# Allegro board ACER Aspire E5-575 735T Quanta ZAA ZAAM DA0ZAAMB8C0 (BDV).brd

Outline 244.9 x 198.7 mm; copper layers: TOP, SGND, IN1, SVCC, IN2, IN3, SGND1, BOTTOM. Coordinates in mm from the lower left corner of the outline.

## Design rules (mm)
constraint set DEFAULT: min track width 0.127
net group DFP-S5W4.5(5)-T13B: nets DDCCLK DDCDAT
net group DFP-S5W5-T: nets USBP0+_R USBP0-_R
net group DFP-S20(10)W16(18)-T123B: nets VGA_VCCSENSE VGA_VSSSENSE
net group W12-T123B: nets PCIE_RCOMPN PCIE_RCOMPP
net group W25-T123B: nets +3V_RTC VCCRTC_2
net group W35-T123B: nets AVCC33 VDD_DAC_33
net group W80-T123B: nets +5V_HDD +5V_ODD
net group W99-T123B: nets USBPWR1 USBPWRD2
net group DFP-S3.5(3)W5(3.5)-T13B: nets VMA_CLK0 VMA_CLK0# VMA_CLK1 VMA_CLK1# VMB_CLK0 VMB_CLK0# VMB_CLK1 VMB_CLK1#
net group DFP-S3.5(3: nets VMA_WCK01 VMA_WCK01# VMA_WCK23 VMA_WCK23# VMA_WCK45 VMA_WCK45# VMA_WCK67 VMA_WCK67# VMB_WCK01 VMB_WCK01# VMB_WCK23 VMB_WCK23# VMB_WCK45 VMB_WCK45# VMB_WCK67 VMB_WCK67#
net group DFP-S4.5(3.5: nets M_A_DQS0 M_A_DQS1 M_A_DQS2 M_A_DQS3 M_A_DQS4 M_A_DQS5 M_A_DQS6 M_A_DQS7 M_A_DQS#0 M_A_DQS#1 M_A_DQS#2 M_A_DQS#3 M_A_DQS#4 M_A_DQS#5 M_A_DQS#6 M_A_DQS#7 M_B_DQS0 M_B_DQS1 M_B_DQS2 M_B_DQS3 M_B_DQS4 M_B_DQS5 M_B_DQS6 M_B_DQS7 M_B_DQS#0 M_B_DQS#1 M_B_DQS#2 M_B_DQS#3 M_B_DQS#4 M_B_DQS#5 M_B_DQS#6 M_B_DQS#7
net group DFP-S5(4: nets M_A_CLK0 M_A_CLK0# M_A_CLK1 M_A_CLK1# M_B_CLK0 M_B_CLK0# M_B_CLK1 M_B_CLK1#
net group DFP-S5(4: nets AUX_CH_N AUX_CH_P C_PEG_TX0 C_PEG_TX1 C_PEG_TX2 C_PEG_TX3 C_PEG_TX#0 C_PEG_TX#1 C_PEG_TX#2 C_PEG_TX#3 CLK_PCIE_LANN CLK_PCIE_LANP CLK_PCIE_VGA CLK_PCIE_VGA# CLK_PCIE_WLANN CLK_PCIE_WLANP CRT_AUXN CRT_AUXP CRT_TXN0 CRT_TXN1 CRT_TXP0 CRT_TXP1 DDI2_AUXN DDI2_AUXP DDI2_TXN0 DDI2_TXN1 DDI2_TXP0 DDI2_TXP1 EDP_AUX#_C EDP_AUX_C EDP_AUXN EDP_AUXP EDP_TXN0 EDP_TXN0_C EDP_TXN1 EDP_TXN1_C EDP_TXN2 EDP_TXN2_C EDP_TXN3 EDP_TXN3_C EDP_TXP0 EDP_TXP0_C EDP_TXP1 EDP_TXP1_C EDP_TXP2 EDP_TXP2_C EDP_TXP3 EDP_TXP3_C LANE0_N LANE0_P LANE1_N LANE1_P NGFF_SSD_CLK NGFF_SSD_CLK# NGFF_SSD_CLK#_C NGFF_SSD_CLK_C PCIE_CLKREQ_NGFF_SSD# PCIE_CLKREQ_NGFF_SSD#_R PCIE_RX5+_LAN PCIE_RX5+_LAN_C PCIE_RX5-_LAN PCIE_RX5-_LAN_C PCIE_RX6+_WLAN PCIE_RX6-_WLAN PCIE_TX5+ PCIE_TX5+_LAN PCIE_TX5- PCIE_TX5-_LAN PCIE_TX6+ PCIE_TX6+_WLAN PCIE_TX6- PCIE_TX6-_WLAN PEG_RX0 PEG_RX1 PEG_RX2 PEG_RX3 PEG_RX#0 PEG_RX#1 PEG_RX#2 PEG_RX#3 PEG_RXN0_C PEG_RXN1_C PEG_RXN2_C PEG_RXN3_C PEG_RXP0_C PEG_RXP1_C PEG_RXP2_C PEG_RXP3_C PEG_TX0 PEG_TX1 PEG_TX2 PEG_TX3 PEG_TX#0 PEG_TX#1 PEG_TX#2 PEG_TX#3 SATA_RXN0 SATA_RXN1 SATA_RXN1_C SATA_RXN3/PEG_RXN9_L0 SATA_RXN3/PEG_RXN9_L0_N SATA_RXN3/PEG_RXN10_L1 SATA_RXN3/PEG_RXN10_L1_N SATA_RXP0 SATA_RXP1 SATA_RXP1_C SATA_RXP3/PEG_RXP9_L0 SATA_RXP3/PEG_RXP9_L0_N SATA_RXP3/PEG_RXP10_L1 SATA_RXP3/PEG_RXP10_L1_N SATA_TXN0 SATA_TXN1 SATA_TXN1_C SATA_TXN3/PEG_TXN9_L0 SATA_TXN3/PEG_TXN9_L0_N SATA_TXN3/PEG_TXN10_L1 SATA_TXN3/PEG_TXN10_L1_N SATA_TXP0 SATA_TXP1 SATA_TXP1_C SATA_TXP3/PEG_TXP9_L0 SATA_TXP3/PEG_TXP9_L0_N SATA_TXP3/PEG_TXP10_L1 SATA_TXP3/PEG_TXP10_L1_N USB2_TYPC_7N_C USB2_TYPC_7P_C USB3_RXN0 USB3_RXN0_R USB3_RXN1 USB3_RXN1_R USB3_RXN2 USB3_RXN3 USB3_RXP0 USB3_RXP0_R USB3_RXP1 USB3_RXP1_R USB3_RXP2 USB3_RXP3 USB3_TXN0 USB3_TXN0_C USB3_TXN0_R USB3_TXN1 USB3_TXN1_C USB3_TXN1_R USB3_TXN2 USB3_TXN3 USB3_TXP0 USB3_TXP0_C USB3_TXP0_R USB3_TXP1 USB3_TXP1_C USB3_TXP1_R USB3_TXP2 USB3_TXP3 USB3_TYPC_RX2N_C USB3_TYPC_RX2N_C_RE USB3_TYPC_RX2N_RE USB3_TYPC_RX2P_C USB3_TYPC_RX2P_C_RE USB3_TYPC_RX2P_RE USB3_TYPC_RX3N_C USB3_TYPC_RX3N_C_RE USB3_TYPC_RX3N_RE USB3_TYPC_RX3P_C USB3_TYPC_RX3P_C_RE USB3_TYPC_RX3P_RE USB3_TYPC_TX2N_C USB3_TYPC_TX2N_C_RE USB3_TYPC_TX2N_R USB3_TYPC_TX2N_RE USB3_TYPC_TX2P_C USB3_TYPC_TX2P_C_RE USB3_TYPC_TX2P_R USB3_TYPC_TX2P_RE USB3_TYPC_TX3N_C USB3_TYPC_TX3N_C_RE USB3_TYPC_TX3N_R USB3_TYPC_TX3N_RE USB3_TYPC_TX3P_C USB3_TYPC_TX3P_C_RE USB3_TYPC_TX3P_R USB3_TYPC_TX3P_RE USBP0+ USBP0+_C USBP0- USBP0-_C USBP1+ USBP1+_R USBP1- USBP1-_R USBP2+ USBP2- USBP3+ USBP3- USBP4+ USBP4- USBP5+ USBP5- USBP6+ USBP6+_R USBP6- USBP6-_R USBP7+ USBP7- USBP8+ USBP8+_PI3 USBP8+_R USBP8+_R_COM USBP8+_R_PI3 USBP8- USBP8-_PI3 USBP8-_R USBP8-_R_COM USBP8-_R_PI3
net group DFP-S5(4.5)W5(4.5)-T3B: nets INT_HDMICLK+ INT_HDMICLK+_C_R INT_HDMICLK- INT_HDMICLK-_C_R INT_HDMITX0N INT_HDMITX0N_C_R INT_HDMITX0P INT_HDMITX0P_C_R INT_HDMITX1N INT_HDMITX1N_C_R INT_HDMITX1P INT_HDMITX1P_C_R INT_HDMITX2N INT_HDMITX2N_C_R INT_HDMITX2P INT_HDMITX2P_C_R
net group DFP-S5W5(3.5: nets HDMI_DDCCLK_MB HDMI_DDCCLK_SW HDMI_DDCDATA_MB HDMI_DDCDATA_SW RTC_X1
net group DFP-S5W5-B: nets SATA_RXN0_C SATA_RXP0_C SATA_TXN0_C SATA_TXP0_C
net group DFP-S6W5(3.5: nets 2ND_MBCLK 2ND_MBDATA CLK_SCLK CLK_SDATA GFX_SCL GFX_SDA I2C0_SCL I2C0_SDA I2C1_SCL I2C1_SCL_C I2C1_SDA I2C1_SDA_C I2C_TP_SCL_R I2C_TP_SDA_R MBCLK MBDATA N17046941 N17047425 PCH_MBCLK0_R PCH_MBDAT0_R SMB_ME1_CLK SMB_ME1_DAT TPCLK TPCLK_R TPDATA TPDATA_R
net group DFP-S10W5(3.5: nets VCCGT_SENSE VCORE_SENSE VCORESS_SENSE VSA_SENSE VSASS_SENSE VSSGT_SENSE
net group DFP-S11(7)W5(3.5: nets LAN_MX0+ LAN_MX0- LAN_MX1+ LAN_MX1- LAN_MX2+ LAN_MX2- LAN_MX3+ LAN_MX3- MDI_0+ MDI_0- MDI_1+ MDI_1- MDI_2+ MDI_2- MDI_3+ MDI_3-
net group DFP-S15W5(3.5: nets LAN_XTAL2 LAN_XTALI RTC_X2 XTAL24_IN XTAL24_OUT XTAL27_IN XTAL27_OUT
net group DFP-S18(13)W5(4.5)-T3B: nets INT_HDMICLK+_C INT_HDMICLK-_C INT_HDMITX0N_C INT_HDMITX0P_C INT_HDMITX1N_C INT_HDMITX1P_C INT_HDMITX2N_C INT_HDMITX2P_C
net group W4.5(5)-T13B: nets CRT_HPD CRTHSYNC CRTHSYNC_B CRTVSYNC CRTVSYNC_B HSYNC PCH_DP_HPD VSYNC
net group W4.5-TB: nets CRT_B1 CRT_BLU CRT_G1 CRT_GRE CRT_R1 CRT_RED
net group W4.25-TB: nets ISOLATEB
net group W5(3.5: nets M_A_DQ0 M_A_DQ1 M_A_DQ2 M_A_DQ3 M_A_DQ4 M_A_DQ5 M_A_DQ6 M_A_DQ7 M_A_DQ8 M_A_DQ9 M_A_DQ10 M_A_DQ11 M_A_DQ12 M_A_DQ13 M_A_DQ14 M_A_DQ15 M_A_DQ16 M_A_DQ17 M_A_DQ18 M_A_DQ19 M_A_DQ20 M_A_DQ21 M_A_DQ22 M_A_DQ23 M_A_DQ24 M_A_DQ25 M_A_DQ26 M_A_DQ27 M_A_DQ28 M_A_DQ29 M_A_DQ30 M_A_DQ31 M_A_DQ32 M_A_DQ33 M_A_DQ34 M_A_DQ35 M_A_DQ36 M_A_DQ37 M_A_DQ38 M_A_DQ39 M_A_DQ40 M_A_DQ41 M_A_DQ42 M_A_DQ43 M_A_DQ44 M_A_DQ45 M_A_DQ46 M_A_DQ47 M_A_DQ48 M_A_DQ49 M_A_DQ50 M_A_DQ51 M_A_DQ52 M_A_DQ53 M_A_DQ54 M_A_DQ55 M_A_DQ56 M_A_DQ57 M_A_DQ58 M_A_DQ59 M_A_DQ60 M_A_DQ61 M_A_DQ62 M_A_DQ63 M_A_DQS8 M_A_DQS#8 M_B_DQ0 M_B_DQ1 M_B_DQ2 M_B_DQ3 M_B_DQ4 M_B_DQ5 M_B_DQ6 M_B_DQ7 M_B_DQ8 M_B_DQ9 M_B_DQ10 M_B_DQ11 M_B_DQ12 M_B_DQ13 M_B_DQ14 M_B_DQ15 M_B_DQ16 M_B_DQ17 M_B_DQ18 M_B_DQ19 M_B_DQ20 M_B_DQ21 M_B_DQ22 M_B_DQ23 M_B_DQ24 M_B_DQ25 M_B_DQ26 M_B_DQ27 M_B_DQ28 M_B_DQ29 M_B_DQ30 M_B_DQ31 M_B_DQ32 M_B_DQ33 M_B_DQ34 M_B_DQ35 M_B_DQ36 M_B_DQ37 M_B_DQ38 M_B_DQ39 M_B_DQ40 M_B_DQ41 M_B_DQ42 M_B_DQ43 M_B_DQ44 M_B_DQ45 M_B_DQ46 M_B_DQ47 M_B_DQ48 M_B_DQ49 M_B_DQ50 M_B_DQ51 M_B_DQ52 M_B_DQ53 M_B_DQ54 M_B_DQ55 M_B_DQ56 M_B_DQ57 M_B_DQ58 M_B_DQ59 M_B_DQ60 M_B_DQ61 M_B_DQ62 M_B_DQ63 M_B_DQS8 M_B_DQS#8
net group W5(3.5: nets ACZ_SDIN CLK_PCI_EC CLK_PCI_LPC CLK_PCI_LPC_C CLK_PCIE_LAN_REQ# CLK_PCIE_REQ0# CLK_PCIE_REQ4# CLK_PCIE_REQ5# CLK_PEGA_REQ# CPU_DRAMRST# DDR3_DRAMRST# H_CPU_SVIDCLK H_CPU_SVIDDAT HDA_BCLK_R HDA_RST#_R HDA_SDO_R HDA_SYNC_R PCH_AZ_CODEC_BITCLK PCH_AZ_CODEC_RST# PCH_AZ_CODEC_SDIN0 PCH_AZ_CODEC_SDOUT PCH_AZ_CODEC_SYNC PCIE_CLKREQ_WLAN# PCIE_REQ_LAN#_R PCLK_TPM PEX_CLKREQ# VR_SVID_ALERT#_VCORE WLAN_CLKREQ#
net group W5(3.5: nets CATERR# CPU_THRMTRIP# DDR_VTTT_PG_CTRL DMIC_CLK DMIC_CLK0_R DMIC_CLK_L DMIC_CLK_L1 DMIC_CLK_L2 DMIC_CLK_L_R0 DMIC_CLK_L_R1 DMIC_DAT DMIC_DAT_L DMIC_DAT_L1 DMIC_DAT_L2 DMIC_DAT_L_R0 DMIC_DAT_L_R1 DMIC_DATA0_R DNBSWON# DPWROK_R H_PECI H_PROCHOT# H_PROCHOT#_R HDMI_MB_HPD HDMI_MB_HPD_R HP_DET_CN IMVP_PWRGD INT_HDMI_HPD INTRUDER# LPC_LAD0 LPC_LAD0_C LPC_LAD1 LPC_LAD1_C LPC_LAD2 LPC_LAD2_C LPC_LAD3 LPC_LAD3_C LPC_LFRAME# LPC_LFRAME#_C PCH_PWRBTN# PCH_RSMRST# PCH_SPI_CLK PCH_SPI_CS0# PCH_SPI_IO2 PCH_SPI_IO3 PCH_SPI_SI PCI_PLTRST# PEGX_RST# PEX_TERMP PLTRST# PWM-VID RSMRST# RTC_RST# SD_CLK_R SIO_RCIN# SP1 SP1=SD_D1 SP2 SP2=SD_D0=MS_D1 SP3 SP3=SD_CLK=MS_D0 SP4 SP4=SD_CMD=MS_D2 SP5 SP5=SD_D3=MS_D3 SP6 SP6=SD_D2=MS_CLK SP7 SP7=SD_WP=MS_BS SP8 SP8=SD_CD# SPI_CLK_8M SPI_HOLD_IO3_ME SPI_SI_8M SPI_SO_8M SPI_WP_IO2_ME SRTC_RST# SYS_PWROK SYS_PWROK_R SYS_RESET# TESTMODE THRMTRIP# USBCOMP VCCST_PWRGD XDP_BPM#0 XDP_BPM#1
net group W5-TB: nets H_CPU_SVIDART# ISL95857_SCLK ISL95857_SDA
net group W6(4.5)-T13B: nets FBA_CMD0 FBA_CMD1 FBA_CMD2 FBA_CMD3 FBA_CMD4 FBA_CMD5 FBA_CMD6 FBA_CMD7 FBA_CMD8 FBA_CMD9 FBA_CMD10 FBA_CMD11 FBA_CMD12 FBA_CMD13 FBA_CMD14 FBA_CMD15 FBA_CMD16 FBA_CMD17 FBA_CMD18 FBA_CMD19 FBA_CMD20 FBA_CMD21 FBA_CMD22 FBA_CMD23 FBA_CMD24 FBA_CMD25 FBA_CMD26 FBA_CMD27 FBA_CMD28 FBA_CMD29 FBA_CMD30 FBA_CMD31 FBA_DBI1 FBA_DBI2 FBA_DBI6 FBA_EDC1 FBA_EDC2 FBA_EDC6 FBB_CMD0 FBB_CMD1 FBB_CMD2 FBB_CMD3 FBB_CMD4 FBB_CMD5 FBB_CMD6 FBB_CMD7 FBB_CMD8 FBB_CMD9 FBB_CMD10 FBB_CMD11 FBB_CMD12 FBB_CMD13 FBB_CMD14 FBB_CMD15 FBB_CMD16 FBB_CMD17 FBB_CMD18 FBB_CMD19 FBB_CMD20 FBB_CMD21 FBB_CMD22 FBB_CMD23 FBB_CMD24 FBB_CMD25 FBB_CMD26 FBB_CMD27 FBB_CMD28 FBB_CMD29 FBB_CMD30 FBB_CMD31 FBB_DBI1 FBB_EDC1 VMA_DQ16 VMA_DQ17 VMA_DQ18 VMA_DQ19 VMA_DQ20 VMA_DQ21 VMA_DQ22 VMA_DQ23 VMA_DQ48 VMA_DQ49 VMA_DQ50 VMA_DQ51 VMA_DQ52 VMA_DQ53 VMA_DQ54 VMA_DQ55 VMB_DQ8 VMB_DQ9 VMB_DQ10 VMB_DQ11 VMB_DQ12 VMB_DQ13 VMB_DQ14 VMB_DQ15
net group W6(4.5: nets FBA_DBI0 FBA_DBI3 FBA_DBI4 FBA_DBI5 FBA_DBI7 FBA_EDC0 FBA_EDC3 FBA_EDC4 FBA_EDC5 FBA_EDC7 FBB_DBI0 FBB_DBI2 FBB_DBI3 FBB_DBI4 FBB_DBI5 FBB_DBI6 FBB_DBI7 FBB_EDC0 FBB_EDC2 FBB_EDC3 FBB_EDC4 FBB_EDC5 FBB_EDC6 FBB_EDC7 VMA_DQ0 VMA_DQ1 VMA_DQ2 VMA_DQ3 VMA_DQ4 VMA_DQ5 VMA_DQ6 VMA_DQ7 VMA_DQ8 VMA_DQ9 VMA_DQ10 VMA_DQ11 VMA_DQ12 VMA_DQ13 VMA_DQ14 VMA_DQ15 VMA_DQ24 VMA_DQ25 VMA_DQ26 VMA_DQ27 VMA_DQ28 VMA_DQ29 VMA_DQ30 VMA_DQ31 VMA_DQ32 VMA_DQ33 VMA_DQ34 VMA_DQ35 VMA_DQ36 VMA_DQ37 VMA_DQ38 VMA_DQ39 VMA_DQ40 VMA_DQ41 VMA_DQ42 VMA_DQ43 VMA_DQ44 VMA_DQ45 VMA_DQ46 VMA_DQ47 VMA_DQ56 VMA_DQ57 VMA_DQ58 VMA_DQ59 VMA_DQ60 VMA_DQ61 VMA_DQ62 VMA_DQ63 VMB_DQ0 VMB_DQ1 VMB_DQ2 VMB_DQ3 VMB_DQ4 VMB_DQ5 VMB_DQ6 VMB_DQ7 VMB_DQ16 VMB_DQ17 VMB_DQ18 VMB_DQ19 VMB_DQ20 VMB_DQ21 VMB_DQ22 VMB_DQ23 VMB_DQ24 VMB_DQ25 VMB_DQ26 VMB_DQ27 VMB_DQ28 VMB_DQ29 VMB_DQ30 VMB_DQ31 VMB_DQ32 VMB_DQ33 VMB_DQ34 VMB_DQ35 VMB_DQ36 VMB_DQ37 VMB_DQ38 VMB_DQ39 VMB_DQ40 VMB_DQ41 VMB_DQ42 VMB_DQ43 VMB_DQ44 VMB_DQ45 VMB_DQ46 VMB_DQ47 VMB_DQ48 VMB_DQ49 VMB_DQ50 VMB_DQ51 VMB_DQ52 VMB_DQ53 VMB_DQ54 VMB_DQ55 VMB_DQ56 VMB_DQ57 VMB_DQ58 VMB_DQ59 VMB_DQ60 VMB_DQ61 VMB_DQ62 VMB_DQ63
net group W8(5.5: nets M_A_A0 M_A_A1 M_A_A2 M_A_A3 M_A_A4 M_A_A5 M_A_A6 M_A_A7 M_A_A8 M_A_A9 M_A_A10 M_A_A11 M_A_A12 M_A_A13 M_A_ACT# M_A_ALERT# M_A_BA#0 M_A_BA#1 M_A_BG#0 M_A_BG#1 M_A_CAS# M_A_CKE0 M_A_CKE1 M_A_CS#0 M_A_CS#1 M_A_ODT0_DIMM M_A_ODT1_DIMM M_A_PARITY M_A_RAS# M_A_WE# M_B_A0 M_B_A1 M_B_A2 M_B_A3 M_B_A4 M_B_A5 M_B_A6 M_B_A7 M_B_A8 M_B_A9 M_B_A10 M_B_A11 M_B_A12 M_B_A13 M_B_ACT# M_B_ALERT# M_B_BA#0 M_B_BA#1 M_B_BG#0 M_B_BG#1 M_B_CAS# M_B_CKE0 M_B_CKE1 M_B_CS#0 M_B_CS#1 M_B_ODT0_DIMM M_B_ODT1_DIMM M_B_PARITY M_B_RAS# M_B_WE#
net group W10-T123B: nets HDMI_5V NV_PLLVDD TH_FAN_POWER VDD33/18
net group W15-T123B: nets FB_CAL_PD_VDDQ HP-L2 HP-L3 HP-R2 HP-R3 HP_JD# LINE1-L LINE1-R LINE1-VREFO-L LINE1-VREFO-R MIC2-VREFO SENSEA SM_RCOMP_0 SM_RCOMP_1 SM_RCOMP_2
net group W20-T13B: nets EDP_RCOMP
net group W20-T123B: nets +1.5VA +3V_MAIN +3V_S5 +5VA +AZA_VDD +VCCPDSW_3P3 +VREF_CA_CPU +VREFDQ_SA_M3 +VREFDQ_SB_M3 +WL_VDD CFG_RCOMP DVDD_IO FB_CAL_TERM_GND PEX_PLLVDD SLEEVE_R V_POA_Q V_POA_R VREFC_VMA1 VREFC_VMA3 VREFD_VMA3
net group W30-T12B: nets EVDD10 LAN_MCT0 LAN_MCT1 LAN_MCT2 LAN_MCT3 TERM9
net group W30-T13B: nets CCD_PWR CRTVDD5 TP_PWR
net group W30-T123B: nets +3V3_SD_SW +3V_EC +3VPCU_EC +3VPCU_ECPLL +5V_KB +5V_KB_R +A3VPCU +VDDQ ECAGND RING2_R
net group W40-T12B: nets LANVCC REGOUT VDD10 VDDREG
net group W40-T13B: nets LCDVCC
net group W40-T123B: nets +3V_WLAN L_SPK+ L_SPK+_1 L_SPK- L_SPK-_1 R_SPK+ R_SPK+_1 R_SPK- R_SPK-_1 RING2 SLEEVE
net group W50-T123B: nets +TPVDD
net group W60-T12B: nets +3V_LAN
net group W60-T13B: nets V_BLIGHT

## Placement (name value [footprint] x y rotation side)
BT1  bat_conn  [BAT-AP-AAA-BAT-054-K01-2P-SMT]  69.91 35.45 90 top
C2  .1u/16v_4  [C0402]  124.14 167.53 270 bottom
C4  .1u/16v_4  [C0402]  123.12 167.53 270 bottom
C7  4.7u/25v_8  [C0805]  111.69 162.83 0 bottom
C8  .1u/16v_4  [C0402]  125.28 171.98 315 bottom
C9  1000p/50v_4  [C0402]  116.13 163.09 90 top
C10  .1u/16v_4  [C0402]  124.64 171.34 315 bottom
C12  .1u/16v_4  [C0402]  126.55 173.25 315 bottom
C13  .1u/16v_4  [C0402]  125.91 172.61 315 bottom
C16  1000p/50v_4  [C0402]  116.77 168.04 270 top
C27  0.1u/10v_4  [C0402]  117.66 168.04 270 top
C29  *2.2u/10v_8  [C0805]  116.54 159.2 270 bottom
C30  22u/6.3v_8  [C0805]  116.54 159.2 90 top
C33  *0.1u/16v_4  [C0402]  113.09 159.91 270 bottom
C34  0.01u/50v_4  [C0402]  115.25 159.91 90 bottom
C35  0.1u/16v_4  [C0402]  113.98 159.91 270 bottom
C41  1u/6.3v_4  [C0402]  110.29 161.44 180 bottom
C114  10u/6.3v_4  [C0402]  132.77 133.5 90 top
C136  1000p/50v_4  [C0402]  145.09 136.29 270 bottom
C144  47u/6.3v_8  [C0805]  125.66 137.94 90 bottom
C148  10u/6.3v_4  [C0402]  110.94 138.94 180 top
C150  47u/6.3v_8  [C0805]  127.69 137.94 90 bottom
C151  10u/6.3v_4  [C0402]  110.97 137.93 180 top
C155  10u/6.3v_4  [C0402]  110.97 136.91 180 top
C157  10u/6.3v_4  [C0402]  134.8 133.5 90 top
C158  10u/6.3v_4  [C0402]  110.97 135.9 180 top
C161  10u/6.3v_4  [C0402]  110.97 134.88 180 top
C164  0.1u/16v_4  [C0402]  147.25 131.97 0 bottom
C165  10u/6.3v_4  [C0402]  133.79 133.5 90 top
C168  *0.1u/16v_4  [C0402]  177.35 35.33 180 top
C169  kbl@4.7u/6.3v_4  [C0402]  225.23 127.02 180 bottom
C170  kbl@0.01u/50v_4  [C0402]  225.23 128.04 180 bottom
C171  22u/6.3v_6  [C0603]  90.73 121.3 270 bottom
C172  1u/6.3v_4  [C0402]  142.8 127.78 90 top
C173  1u/6.3v_4  [C0402]  139.76 127.27 90 top
C174  1u/6.3v_4  [C0402]  132.52 129.94 90 top
C176  1u/6.3v_4  [C0402]  131.63 128.92 90 top
C178  22u/6.3v_6  [C0603]  92.39 113.18 270 bottom
C179  1u/6.3v_4  [C0402]  138.74 127.27 90 top
C181  1u/6.3v_2  [C0201]  121.47 121.94 0 top
C182  47u/6.3v_8  [C0805]  137.22 127.27 90 top
C184  1u/6.3v_2  [C0201]  115.75 118 90 top
C185  10u/6.3v_4  [C0402]  94.16 115.08 270 top
C186  10u/6.3v_4  [C0402]  93.15 115.08 270 top
C187  kbl@2.2u/6.3v_4  [C0402]  224.97 121.81 270 bottom
C188  1u/6.3v_2  [C0201]  97.47 115.34 270 top
C189  1u/6.3v_2  [C0201]  121.47 121.18 0 top
C190  47u/6.3v_8  [C0805]  92.51 124.48 90 bottom
C191  1u/6.3v_4  [C0402]  140.26 124.35 270 top
C192  1u/6.3v_4  [C0402]  136.96 124.35 270 top
C193  1u/6.3v_2  [C0201]  100.51 116.35 270 top
C194  1u/6.3v_4  [C0402]  99.93 118.13 270 top
C195  1u/6.3v_2  [C0201]  101.28 116.35 270 top
C196  1u/6.3v_2  [C0201]  122.36 121.94 180 top
C197  1u/6.3v_2  [C0201]  100.79 117.85 90 top
C198  1u/6.3v_2  [C0201]  102.04 116.35 270 top
C199  47u/6.3v_8  [C0805]  88.58 124.48 90 bottom
C200  1u/6.3v_2  [C0201]  122.48 120.54 180 top
C201  1u/6.3v_2  [C0201]  122.9 119.44 180 top
C202  22u/6.3v_6  [C0603]  114.74 112.92 0 top
C203  22u/6.3v_6  [C0603]  122.63 110.16 0 top
C204  1u/6.3v_2  [C0201]  101.5 117.85 90 top
C205  1u/6.3v_4  [C0402]  107.12 102.53 180 top
C206  1u/6.3v_2  [C0201]  99.75 116.35 270 top
C207  1u/6.3v_2  [C0201]  124.17 118.75 0 top
C209  1u/6.3v_2  [C0201]  122.87 118.64 180 top
C212  1u/6.3v_2  [C0201]  116.52 118 90 top
C214  1u/6.3v_2  [C0201]  122.61 107.97 180 top
C215  1u/6.3v_2  [C0201]  133.22 146.39 180 top
C216  1u/6.3v_4  [C0402]  125.18 117.24 180 top
C217  1u/6.3v_4  [C0402]  139.25 124.35 270 top
C218  10u/6.3v_4  [C0402]  98.61 117.11 90 top
C219  22u/6.3v_6  [C0603]  122.61 115.97 0 top
C221  10u/6.3v_4  [C0402]  125.19 116.29 0 top
C222  1u/6.3v_2  [C0201]  133.22 147.33 180 top
C223  10u/6.3v_4  [C0402]  97.47 117.11 90 top
C224  22u/6.3v_6  [C0603]  117.91 116.86 180 top
C225  *1u/6.3v_4  [C0402]  137.85 124.35 270 top
C226  22u/6.3v_6  [C0603]  122.61 117.37 0 top
C227  1u/6.3v_4  [C0402]  120.17 119.65 90 top
C228  1u/6.3v_2  [C0201]  133.17 148.12 180 top
C229  10u/6.3v_4  [C0402]  125.19 115.32 0 top
C230  1u/6.3v_4  [C0402]  141.92 116.1 90 top
C232  10u/6.3v_4  [C0402]  96.2 115.08 270 top
C233  22u/6.3v_6  [C0603]  117.91 115.46 180 top
C235  1u/6.3v_2  [C0201]  120.45 107.84 270 top
C236  22u/6.3v_6  [C0603]  115.37 116.22 0 top
C237  1u/6.3v_2  [C0201]  117.79 110.38 0 top
C238  10u/6.3v_4  [C0402]  125.19 114.18 0 top
C239  1u/6.3v_2  [C0201]  107.63 103.65 90 top
C240  1u/6.3v_2  [C0201]  98.23 115.34 270 top
C241  1u/6.3v_4  [C0402]  102.34 117.93 270 top
C242  1u/6.3v_4  [C0402]  127.2 113.7 0 top
C243  22u/6.3v_6  [C0603]  117.79 112.67 180 top
C244  0.1u/16v_4  [C0402]  32.95 72.28 90 top
C245  1u/6.3v_2  [C0201]  120.58 109.87 0 top
C246  1u/6.3v_2  [C0201]  119.69 107.84 270 top
C247  10u/6.3v_4  [C0402]  125.19 113.16 0 top
C248  47u/6.3v_8  [C0805]  94.54 124.48 90 bottom
C249  1u/6.3v_2  [C0201]  127.48 112.73 180 top
C250  1u/6.3v_4  [C0402]  144.71 113.3 0 top
C251  22u/6.3v_6  [C0603]  122.63 111.49 0 top
C252  1u/6.3v_4  [C0402]  119.56 110.33 270 top
C254  10u/6.3v_4  [C0402]  125.19 112.15 0 top
C255  22u/6.3v_6  [C0603]  117.79 111.4 180 top
C256  1u/6.3v_4  [C0402]  152.84 112.03 0 top
C257  10u/6.3v_4  [C0402]  122.83 113.59 180 top
C258  10u/6.3v_4  [C0402]  126.42 141.37 90 top
C259  10u/6.3v_4  [C0402]  122.83 112.58 180 top
C260  1u/6.3v_2  [C0201]  127.48 111.77 180 top
C261  1u/6.3v_4  [C0402]  152.84 110.64 180 top
C262  1u/6.3v_2  [C0201]  121.85 107.84 270 top
C263  10u/6.3v_4  [C0402]  125.19 111.13 0 top
C264  1u/6.3v_2  [C0201]  116.2 110.75 270 top
C265  *1u/6.3v_4  [C0402]  142.93 116.1 270 top
C266  1u/6.3v_2  [C0201]  115.23 110.75 270 top
C267  1u/6.3v_2  [C0201]  127.48 110.8 180 top
C268  1u/6.3v_4  [C0402]  152.84 109.24 0 top
C269  1u/6.3v_2  [C0201]  121.11 107.84 270 top
C270  *1u/6.3v_4  [C0402]  146.49 112.92 90 top
C272  22u/6.3v_6  [C0603]  122.61 114.7 0 top
C273  22u/6.3v_6  [C0603]  121.21 123.21 0 top
C274  22u/6.3v_6  [C0603]  96.58 113.18 270 bottom
C275  22u/6.3v_6  [C0603]  95.18 113.18 270 bottom
C276  *gt3@22u/6.3v_6  [C0603]  113.85 107.89 0 top
C277  22u/6.3v_6  [C0603]  114.61 114.95 0 top
C278  1u/6.3v_2  [C0201]  127.48 109.78 180 top
C279  *gt3@10u/6.3v_4  [C0402]  114.24 110.34 270 top
C280  *gt3@10u/6.3v_4  [C0402]  111.98 110.34 270 top
C281  *gt3@10u/6.3v_4  [C0402]  113.28 110.34 270 top
C282  22u/6.3v_6  [C0603]  117.73 119.2 180 top
C283  10u/6.3v_4  [C0402]  124.43 109.56 270 top
C284  10u/6.3v_4  [C0402]  125.44 109.56 270 top
C285  1u/6.3v_2  [C0201]  122.93 109.23 180 top
C286  10u/6.3v_4  [C0402]  117.53 109.11 270 top
C288  10u/6.3v_4  [C0402]  127.48 107.85 180 top
C289  22u/6.3v_6  [C0603]  118.69 106.91 270 top
C290  *gt3@10u/6.3v_4  [C0402]  110.17 107.84 180 top
C291  *gt3@10u/6.3v_4  [C0402]  111.82 107.84 0 top
C292  *1u/6.3v_4  [C0402]  152.84 108.1 0 top
C297  1u/6.3v_2  [C0201]  124.73 107.83 270 top
C298  1u/6.3v_2  [C0201]  125.83 107.83 180 top
C299  1u/6.3v_2  [C0201]  117.52 107.73 180 top
C300  *220p/50v_4  [C0402]  10.85 84.09 90 top
C301  0.1u/16v_4  [C0402]  9.84 84.09 270 top
C302  *gt3@22u/6.3v_6  [C0603]  96.7 118.64 90 bottom
C303  *gt3@22u/6.3v_6  [C0603]  95.31 118.64 90 bottom
C304  *0.1u/16v_4  [C0402]  12.88 84.09 90 top
C305  *0.22u/6.3v_4  [C0402]  11.87 84.09 270 top
C307  *gt3@22u/6.3v_6  [C0603]  96.7 121.3 270 bottom
C308  1u/6.3v_2  [C0201]  126.71 103.64 90 top
C310  *gt3@22u/6.3v_6  [C0603]  88.19 113.18 270 bottom
C311  1u/6.3v_2  [C0201]  122.14 103.13 270 top
C312  1u/6.3v_2  [C0201]  118.71 103 270 top
C313  1u/6.3v_2  [C0201]  119.86 103 90 top
C314  *0.1u/16v_4  [C0402]  146.61 116.35 270 top
C315  0.1u/16v_4  [C0402]  28 71.77 0 top
C316  *gt3@10u/6.3v_4  [C0402]  96.32 117.11 90 top
C317  *gt3@10u/6.3v_4  [C0402]  95.18 115.08 270 top
C318  10u/6.3v_4  [C0402]  117.19 102.24 180 top
C319  *5.6p/16v_4  [C0402]  12.38 76.09 90 top
C320  5.6p/16v_4  [C0402]  16.19 75.84 270 top
C321  2.2u/6.3v_4  [C0402]  78.42 121.94 270 bottom
C322  1u/6.3v_4  [C0402]  157.28 89.94 270 top
C323  10u/6.3v_4  [C0402]  127.56 101.75 270 top
C324  *gt3@10u/6.3v_4  [C0402]  95.18 117.11 90 top
C325  10u/6.3v_4  [C0402]  125.53 93.24 270 bottom
C326  10u/6.3v_4  [C0402]  119.98 101.35 0 top
C327  10u/6.3v_4  [C0402]  125.7 101.35 180 top
C328  10u/6.3v_4  [C0402]  122.52 101.33 180 top
C329  0.1u/16v_4  [C0402]  28 70.89 0 top
C330  *15p/50v_4  [C0402]  228.66 104.54 270 top
C331  0.1u/16v_4  [C0402]  28 69.74 0 top
C332  0.1u/16v_4  [C0402]  163 85.36 0 bottom
C333  *5.6p/16v_4  [C0402]  12.38 73.81 270 top
C334  5.6p/16v_4  [C0402]  16.19 73.81 270 top
C335  0.1u/16v_4  [C0402]  28 68.85 0 top
C336  *5.6p/16v_4  [C0402]  11.61 71.77 270 top
C337  5.6p/16v_4  [C0402]  15.42 71.52 270 top
C338  **0.1u/16v_4  [C0402]  201.48 189.25 0 top
C339  **0.1u/16v_4  [C0402]  199.07 189.12 180 top
C340  10u/6.3v_6  [C0603]  201.48 191.92 180 top
C341  0.1u/16v_4  [C0402]  28 65.68 0 top
C343  0.1u/16v_4  [C0402]  28 66.57 0 top
C344  *ioac@1000p/50v_4  [C0402]  204.65 192.25 0 top
C345  *ioac@0.1u/16v_4  [C0402]  206.56 192.25 180 top
C346  *0.1u/16v_4  [C0402]  199.07 190.14 180 top
C347  *10u/6.3v_6  [C0603]  201.48 190.52 180 top
C348  0.1u/16v_4  [C0402]  143.06 110 90 top
C349  1u/6.3v_4  [C0402]  142.04 110 270 top
C350  *0.1u/16v_4  [C0402]  42.47 62.38 270 top
C351  8.2p/50v_4  [C0402]  139.63 96.67 90 bottom
C352  0.1u/16v_4  [C0402]  158.3 89.94 90 top
C353  0.1u/16v_4  [C0402]  83.88 82.44 180 bottom
C354  0.1u/16v_4  [C0402]  35.87 78.51 270 top
C355  0.1u/16v_4  [C0402]  36.89 78.25 270 top
C356  10u/6.3v_4  [C0402]  82.35 82.06 90 bottom
C357  *10p/50v_4  [C0402]  86.42 84.73 180 bottom
C360  10p/50v_4  [C0402]  83.88 83.59 180 bottom
C361  *4.7u/6.3v_4  [C0402]  40.75 78.89 90 top
C362  8.2p/50v_4  [C0402]  139.63 93.24 270 bottom
C363  0.1u/16v_4  [C0402]  43.49 68.98 0 top
C364  0.01u/50v_4  [C0402]  36.12 88.79 90 bottom
C365  0.1u/16v_4  [C0402]  34.73 78.51 270 top
C366  10u/6.3v_6  [C0603]  39.43 62.25 90 top
C367  0.1u/16v_4  [C0402]  43.36 62.38 270 top
C368  *ioac@1000p/50v_4  [C0402]  48.95 65.17 180 top
C369  tyc@0.1u/16v_4_x7r  [C0402]  37.52 119.02 0 top
C370  0.1u/16v_4  [C0402]  41.59 62.38 90 top
C371  *0.1u/16v_4  [C0402]  136.2 80.66 180 bottom
C373  *10u/6.3v_4  [C0402]  136.2 79.52 180 bottom
C374  *10p/50v_4  [C0402]  82.73 85.49 180 bottom
C376  *10p/50v_4  [C0402]  136.2 81.81 180 bottom
C377  *0.1u/16v_4  [C0402]  40.7 62.38 270 top
C378  *10p/50v_4  [C0402]  133.66 81.81 0 bottom
C379  *10p/50v_4  [C0402]  131.63 80.66 180 bottom
C380  1u/6.3v_4  [C0402]  78.03 46.63 180 top
C381  1u/6.3v_4  [C0402]  76.26 45.99 180 top
C382  1u/6.3v_4  [C0402]  78.03 48.03 180 top
C383  *220p/50v_4  [C0402]  14.53 54.12 90 top
C386  0.1u/16v_4_x7r  [C0402]  20.76 43.33 90 top
C387  0.1u/16v_4  [C0402]  25.2 51.84 0 top
C389  0.1u/16v_4  [C0402]  25.2 50.82 0 top
C394  tyc@0.1u/16v_4_x7r  [C0402]  35.74 116.1 0 top
C398  0.1u/16v_4  [C0402]  25.2 45.74 0 top
C405  0.1u/16v_4  [C0402]  25.2 44.72 0 top
C406  0.1u/16v_4  [C0402]  25.2 47.77 0 top
C407  0.1u/16v_4  [C0402]  25.2 46.76 0 top
C408  0.1u/16v_4  [C0402]  25.2 49.8 0 top
C411  0.1u/16v_4  [C0402]  25.2 48.79 0 top
C412  gs@10u/6.3v_6  [C0603]  218.5 61.87 180 bottom
C413  0.1u/16v_4_x7r  [C0402]  22.92 52.98 180 top
C424  1u/6.3v_4  [C0402]  25.71 37.74 90 top
C425  *22p/50v_4  [C0402]  215.45 52.86 90 bottom
C428  gs@0.1u/16v_4  [C0402]  224.92 56.03 180 bottom
C431  *33p/50v_4  [C0402]  220.99 61.61 0 bottom
C435  *0.1u/16v_4  [C0402]  224.08 44.47 90 bottom
C436  0.01u/50v_4  [C0402]  225.23 44.47 90 bottom
C437  0.01u/50v_4  [C0402]  222.94 44.47 90 bottom
C438  10u/6.3v_6  [C0603]  221.8 47.9 270 bottom
C450  0.1u/16v_4  [C0402]  20 39.26 90 top
C451  470p/50v_4  [C0402]  18.98 39.26 90 top
C452  100u/6.3v_1206  [C1206]  17.2 37.87 90 top
C453  *0.1u/16v_4  [C0402]  221.93 44.47 90 bottom
C454  *33p/50v_4  [C0402]  224.92 57.93 180 bottom
C456  *10u/6.3v_4  [C0402]  201.73 50.57 180 bottom
C457  *100u/6.3v_3528  [C3528]  224.21 48.41 270 bottom
C458  *1.6p/50v_4  [C0402]  20.38 34.94 270 top
C459  0.1u/16v_4  [C0402]  23.42 34.56 0 top
C460  *1.6p/50v_4  [C0402]  20.38 33.17 90 top
C461  0.1u/16v_4  [C0402]  23.42 33.55 0 top
C462  0.1u/16v_4  [C0402]  16.13 32.91 270 top
C469  *1.6p/50v_4  [C0402]  23.04 30.88 90 top
C475  *1.6p/50v_4  [C0402]  23.04 29.23 270 top
C476  0.1u/16v_4  [C0402]  208.84 47.39 270 bottom
C477  100p/50v_4  [C0402]  209.73 47.39 90 bottom
C481  10u/6.3v_4  [C0402]  205.42 49.3 270 bottom
C482  0.1u/16v_4  [C0402]  188.02 36.72 90 top
C483  1u/10v_4  [C0402]  18.85 29.61 0 top
C484  10u/6.3v_4  [C0402]  200.21 46.88 0 bottom
C485  0.1u/16v_4  [C0402]  199.95 48.03 0 bottom
C487  100u/6.3v_1206  [C1206]  23.93 25.42 180 top
C488  10p/50v_4  [C0402]  202.62 49.3 270 bottom
C489  10u/6.3v_4  [C0402]  207.32 48.15 180 bottom
C490  *10p/50v_4  [C0402]  191.32 36.85 90 bottom
C491  1u/6.3v_4  [C0402]  189.54 35.45 180 bottom
C492  0.1u/16v_4  [C0402]  207.32 47.26 180 bottom
C493  *22p/50v_4  [C0402]  204.53 47.26 90 bottom
C494  *1u/10v_4  [C0402]  194.62 44.85 270 bottom
C495  0.1u/16v_4  [C0402]  169.73 32.53 270 bottom
C496  0.1u/16v_4  [C0402]  24.82 28.21 0 top
C497  470p/50v_4  [C0402]  20.12 21.61 270 top
C498  0.1u/16v_4  [C0402]  17.96 20.72 90 top
C499  0.1u/16v_4  [C0402]  18.85 20.72 90 top
C500  0.1u/16v_4  [C0402]  197.8 46.25 0 bottom
C501  10u/6.3v_4  [C0402]  197.8 45.1 0 bottom
C502  0.1u/16v_4  [C0402]  16.06 14.88 270 top
C504  0.01u/50v_4  [C0402]  224.47 37.74 270 bottom
C505  *1.6p/50v_4  [C0402]  17.84 17.55 0 top
C507  0.01u/50v_4  [C0402]  223.45 37.74 270 bottom
C508  0.1u/16v_4  [C0402]  179.38 45.61 270 bottom
C509  0.1u/16v_4  [C0402]  197.8 43.83 0 bottom
C510  10u/6.3v_4  [C0402]  197.8 41.93 0 bottom
C511  *1.6p/50v_4  [C0402]  19.61 17.55 180 top
C513  0.01u/50v_4  [C0402]  224.47 33.42 270 bottom
C514  0.1u/16v_4  [C0402]  185.4 48.43 270 bottom
C515  *10u/6.3v_6  [C0603]  213.16 35.45 0 bottom
C516  10u/6.3v_6  [C0603]  168.59 28.59 180 bottom
C517  *1.6p/50v_4  [C0402]  19.74 8.53 0 top
C518  *1.6p/50v_4  [C0402]  17.84 8.53 180 top
C519  10u/6.3v_4  [C0402]  210.88 42.06 180 bottom
C520  10u/6.3v_4  [C0402]  198.43 38.75 90 bottom
C522  0.01u/50v_4  [C0402]  223.45 33.42 270 bottom
C523  *10u/6.3v_6  [C0603]  206.69 30.88 270 bottom
C524  0.1u/16v_4  [C0402]  197.41 38.75 90 bottom
C525  *0.1u/16v_4  [C0402]  213.29 34.18 180 bottom
C526  *0.1u/16v_4  [C0402]  207.32 34.44 0 bottom
C527  10u/6.3v_4  [C0402]  201.86 36.6 90 bottom
C528  1u/6.3v_4  [C0402]  201.1 38.63 270 bottom
C529  10u/6.3v_4  [C0402]  199.32 39.52 270 bottom
C530  1u/6.3v_4  [C0402]  202.88 36.6 90 bottom
C532  0.1u/16v_4  [C0402]  209.23 37.99 180 bottom
C534  10u/6.3v_4  [C0402]  207.7 36.98 90 bottom
C535  2.2u/6.3v_4  [C0402]  206.69 36.98 270 bottom
C536  10u/6.3v_4  [C0402]  209.23 36.98 180 bottom
C537  *1000p/50v_4  [C0402]  206.3 39.9 270 top
C538  *0.1u/16v_4  [C0402]  206.18 10.94 90 bottom
C541  1u/6.3v_4  [C0402]  195.89 41.93 0 bottom
C545  *68p/50v_4  [C0402]  79.69 11.07 180 top
C546  *68p/50v_4  [C0402]  79.69 12.34 180 top
C547  100p/50v_4  [C0402]  205.67 22.37 90 bottom
C548  *68p/50v_4  [C0402]  79.69 13.61 180 top
C549  4.7u/6.3v_4  [C0402]  202.11 28.98 0 bottom
C550  100p/50v_4  [C0402]  201.48 22.37 90 bottom
C551  *68p/50v_4  [C0402]  79.69 14.88 180 top
C552  4.7u/6.3v_4  [C0402]  204.91 28.98 0 bottom
C553  100p/50v_4  [C0402]  202.88 22.37 90 bottom
C554  100p/50v_4  [C0402]  204.27 22.37 90 bottom
C555  39p/50v_4  [C0402]  58.35 16.91 90 top
C556  4.7u/6.3v_4  [C0402]  71.56 14.12 270 top
C577  0.1u/16v_4  [C0402]  118.29 171.47 90 top
C578  1000p/50v_4  [C0402]  119.18 171.47 90 top
C580  *1u/6.3v_4  [C0402]  118.04 165.37 270 bottom
C581  *1u/6.3v_4  [C0402]  119.06 165.37 90 bottom
C628  *0.1u/16v_4  [C0402]  94.29 135.53 180 bottom
C641  10u/6.3v_4  [C0402]  138.74 133.5 90 top
C642  10u/6.3v_4  [C0402]  136.07 133.5 90 top
C643  10u/6.3v_4  [C0402]  137.34 133.5 90 top
C645  47u/6.3v_8  [C0805]  127.44 133.88 270 bottom
C647  10u/6.3v_4  [C0402]  128.45 141.37 90 top
C648  0.1u/16v_4  [C0402]  128.45 130.45 270 bottom
C649  0.1u/16v_4  [C0402]  127.44 130.45 270 bottom
C650  47u/6.3v_8  [C0805]  125.02 129.31 0 bottom
C651  10u/6.3v_4  [C0402]  127.44 141.37 90 top
C652  ev@0.22u/10v_4  [C0402]  133.66 127.91 90 bottom
C653  ev@0.22u/10v_4  [C0402]  134.68 127.91 270 bottom
C654  ev@0.22u/10v_4  [C0402]  130.99 132.99 90 bottom
C655  ev@0.22u/10v_4  [C0402]  135.31 129.81 90 bottom
C656  ev@0.22u/10v_4  [C0402]  136.33 129.81 90 bottom
C657  10u/6.3v_4  [C0402]  130.49 141.37 90 top
C658  10p/50v_4  [C0402]  114.1 128.8 0 bottom
C659  47u/6.3v_8  [C0805]  125.02 131.34 0 bottom
C660  ev@0.22u/10v_4  [C0402]  132.01 132.99 90 bottom
C661  ev@0.22u/10v_4  [C0402]  133.53 132.99 90 bottom
C662  ev@0.22u/10v_4  [C0402]  134.55 132.99 90 bottom
C663  10u/6.3v_4  [C0402]  124.64 127.91 180 bottom
C664  10u/6.3v_4  [C0402]  120.83 127.02 0 bottom
C665  10p/50v_4  [C0402]  112.32 128.8 180 bottom
C666  47u/6.3v_8  [C0805]  125.53 133.88 270 bottom
C667  10u/6.3v_4  [C0402]  119.18 127.91 0 bottom
C668  0.1u/16v_4  [C0402]  126.8 127.53 270 bottom
C669  0.1u/16v_4  [C0402]  127.82 127.53 270 bottom
C672  1u/6.3v_4  [C0402]  148.65 119.91 270 bottom
C673  10u/6.3v_4  [C0402]  122.61 127.02 180 bottom
C674  10u/6.3v_4  [C0402]  124.64 127.02 180 bottom
C675  10u/6.3v_4  [C0402]  119.18 127.02 0 bottom
C676  10u/6.3v_4  [C0402]  129.47 141.37 90 top
C677  1u/6.3v_4  [C0402]  131.76 127.53 90 bottom
C678  10u/6.3v_4  [C0402]  120.83 127.91 0 bottom
C679  10u/6.3v_4  [C0402]  122.61 127.91 180 bottom
C680  *1u/6.3v_4  [C0402]  140.77 127.27 270 top
C681  *gt3@1u/6.3v_2  [C0201]  94.06 110.87 270 top
C682  *gt3@10u/6.3v_4  [C0402]  92.39 111.02 270 top
C683  *gt3@1u/6.3v_4  [C0402]  92.03 107.97 270 top
C684  *gt3@1u/6.3v_2  [C0201]  93.35 110.87 270 top
C685  *gt3@1u/6.3v_2  [C0201]  94.77 110.87 270 top
C686  *gt3@10u/6.3v_4  [C0402]  96.96 127.53 0 bottom
C687  *gt3@10u/6.3v_4  [C0402]  96.96 128.42 0 bottom
C688  *gt3@1u/6.3v_4  [C0402]  91.06 107.97 270 top
C689  *gt3@1u/6.3v_4  [C0402]  90.1 107.97 270 top
C690  47u/6.3v_8  [C0805]  86.67 124.48 90 bottom
C691  22u/6.3v_6  [C0603]  93.78 113.18 270 bottom
C692  22u/6.3v_6  [C0603]  93.78 118.64 90 bottom
C693  22u/6.3v_6  [C0603]  89.59 113.18 270 bottom
C694  22u/6.3v_6  [C0603]  89.34 118.64 90 bottom
C695  1u/6.3v_4  [C0402]  149.54 119.91 90 bottom
C696  47u/6.3v_8  [C0805]  84.77 124.48 90 bottom
C697  47u/6.3v_8  [C0805]  90.48 124.48 90 bottom
C698  1u/6.3v_4  [C0402]  135.69 122.96 0 top
C699  47u/6.3v_8  [C0805]  134.55 126.64 180 top
C700  1u/6.3v_4  [C0402]  92.89 105.3 90 bottom
C701  1u/6.3v_4  [C0402]  91.88 105.3 90 bottom
C702  47u/6.3v_8  [C0805]  96.32 124.48 90 bottom
C703  22u/6.3v_6  [C0603]  90.99 113.18 270 bottom
C704  22u/6.3v_6  [C0603]  92.13 121.3 270 bottom
C705  22u/6.3v_6  [C0603]  92.13 118.64 90 bottom
C706  22u/6.3v_6  [C0603]  90.73 118.64 90 bottom
C707  22u/6.3v_6  [C0603]  89.34 121.3 270 bottom
C708  *gt3@10u/6.3v_4  [C0402]  93.78 106.57 0 top
C709  *gt3@10u/6.3v_4  [C0402]  93.78 107.46 0 top
C710  1u/6.3v_4  [C0402]  90.86 105.3 90 bottom
C711  1u/6.3v_4  [C0402]  89.85 105.3 90 bottom
C712  1u/6.3v_4  [C0402]  144.58 109.75 0 bottom
C713  0.1u/16v_4  [C0402]  11.11 87.27 90 bottom
C714  *10p/50v_4  [C0402]  13.39 82.44 0 top
C716  *33p/50v_4  [C0402]  13.39 81.43 180 top
C718  *33p/50v_4  [C0402]  13.39 79.39 180 top
C719  *.01u/50v_4  [C0402]  78.42 119.91 90 bottom
C720  0.1u/16v_4  [C0402]  14.03 87.27 90 bottom
C721  0.01u/50v_4  [C0402]  229.8 108.6 0 bottom
C723  2.2u/6.3v_4  [C0402]  79.94 122.32 0 bottom
C724  *10p/50v_4  [C0402]  13.39 80.41 180 top
C726  0.01u/50v_4  [C0402]  229.8 109.62 0 bottom
C728  .01u/50v_4  [C0402]  79.94 121.18 0 bottom
C730  *0.1u/16v_4  [C0402]  229.8 107.59 0 bottom
C731  0.1u/16v_4  [C0402]  199.07 191.15 0 top
C732  0.1u/16v_4  [C0402]  144.58 100.22 180 bottom
C733  *0.1u/16v_4  [C0402]  229.8 110.76 0 bottom
C735  0.1u/16v_4  [C0402]  201.48 188.23 180 top
C737  10u/6.3v_6  [C0603]  229.29 106.57 0 bottom
C739  22p/50v_4  [C0402]  129.72 95.4 270 bottom
C740  *100u/6.3v_3528  [C3528]  229.16 103.02 90 bottom
C742  *10p/50v_4  [C0402]  130.87 95.4 270 bottom
C743  0.01u/50v_4  [C0402]  229.93 99.84 0 bottom
C744  0.01u/50v_4  [C0402]  229.93 98.83 0 bottom
C746  1000p/3kv_1808  [CC1808]  29.77 93.49 0 bottom
C747  *22p/50v_4  [C0402]  181.16 53.87 90 top
C748  1u/6.3v_4  [C0402]  152.96 89.55 180 top
C749  0.01u/50v_4  [C0402]  229.16 85.36 0 bottom
C750  *0.1u/16v_4  [C0402]  152.58 92.98 270 top
C751  0.01u/50v_4  [C0402]  229.16 84.35 0 bottom
C752  ioac@0.1u/25v_4  [C0402]  225.61 109.37 180 top
C753  0.1u/16v_4  [C0402]  199.07 192.17 0 top
C754  0.1u/16v_4  [C0402]  183.32 56.66 90 top
C755  0.1u/16v_4  [C0402]  199.07 188.23 0 top
C756  **ioac@1000p/50v_4  [C0402]  206.56 188.34 180 top
C757  0.1u/16v_4  [C0402]  39.55 78.89 270 top
C758  *1u/6.3v_4  [C0402]  43.87 77.11 270 top
C759  **ioac@0.1u/16v_4  [C0402]  204.65 188.34 0 top
C760  0.1u/16v_4  [C0402]  39.05 66.95 90 top
C761  *0.1u/16v_4  [C0402]  44.76 77.11 270 top
C762  0.1u/16v_4  [C0402]  42.98 77.11 270 top
C763  *0.1u/16v_4  [C0402]  200.72 185.57 0 bottom
C764  *0.1u/16v_4  [C0402]  219.89 72.54 90 top
C765  *0.1u/25v_4  [C0402]  219.51 67.84 180 top
C766  tpm@0.1u/16v_4  [C0402]  170.11 66.06 180 bottom
C767  tpm@10u/6.3v_6  [C0603]  170.24 64.79 180 bottom
C768  tpm@0.1u/16v_4  [C0402]  168.84 74.31 180 bottom
C770  0.1u/16v_4  [C0402]  169.98 42.69 270 bottom
C771  0.1u/16v_4  [C0402]  179.51 25.55 180 bottom
C772  0.1u/16v_4  [C0402]  186.87 45.61 270 bottom
C774  tpm@0.1u/16v_4  [C0402]  162.74 70.89 0 bottom
C775  tpm@0.1u/16v_4  [C0402]  165.79 65.42 90 bottom
C776  tpm@10u/6.3v_6  [C0603]  164.78 65.3 90 bottom
C777  0.1u/16v_4  [C0402]  179.89 47.64 270 bottom
C778  0.1u/16v_4  [C0402]  187 36.09 90 top
C780  0.1u/16v_4  [C0402]  189.54 31.64 180 bottom
C781  0.1u/16v_4  [C0402]  133.03 17.29 270 bottom
C783  0.1u/16v_4  [C0402]  117.5 18.18 0 bottom
C785  *0.1u/16v_4  [C0402]  216.85 37.48 180 bottom
C786  *1000p/50v_4  [C0402]  130.1 17.16 0 bottom
C787  *0.1u/16v_4  [C0402]  119.53 18.18 180 bottom
C788  *0.1u/16v_4  [C0402]  121.56 18.18 0 bottom
C790  0.22u/10v_4  [C0402]  132.14 17.29 270 bottom
C793  1u/6.3v_4  [C0402]  145.09 119.4 0 bottom
C794  *1u/6.3v_4  [C0402]  139.63 121.05 90 top
C796  180p/50v_4  [C0402]  172.27 45.61 270 bottom
C797  180p/50v_4  [C0402]  181.92 39.52 0 top
C798  180p/50v_4  [C0402]  169.47 26.18 270 bottom
C799  180p/50v_4  [C0402]  171.25 43.58 270 bottom
C800  180p/50v_4  [C0402]  189.54 27.2 0 bottom
C801  180p/50v_4  [C0402]  183.72 47.39 180 bottom
C802  180p/50v_4  [C0402]  226.62 104.54 90 top
C803  180p/50v_4  [C0402]  133.53 178.71 0 bottom
C804  180p/50v_4  [C0402]  121.85 172.87 180 top
C805  180p/50v_4  [C0402]  149.79 17.8 90 bottom
C806  0.1u/16v_4  [C0402]  148.65 99.21 180 bottom
C807  tpm@33p/50v_4  [C0402]  162.74 68.85 0 bottom
C808  0.1u/16v_4  [C0402]  143.31 131.97 180 bottom
C811  *0.1u/16v_4  [C0402]  190.94 53.87 270 bottom
C812  *0.1u/16v_4  [C0402]  197.92 31.13 180 bottom
C813  *0.1u/16v_4  [C0402]  158.43 33.93 0 bottom
C814  1000p/50v_4  [C0402]  103.05 132.48 90 bottom
C815  *1000p/50v_4  [C0402]  99.24 132.48 90 bottom
C816  *1000p/50v_4  [C0402]  99.88 130.58 270 bottom
C817  *1000p/50v_4  [C0402]  98.86 130.58 270 bottom
C818  *1000p/50v_4  [C0402]  100.26 132.48 90 bottom
C819  *1000p/50v_4  [C0402]  101.28 132.48 90 bottom
C821  180p/50v_4  [C0402]  201.1 179.22 0 bottom
C822  180p/50v_4  [C0402]  189.54 32.53 180 bottom
C823  *1000p/50v_4  [C0402]  143.69 136.29 90 bottom
C824  *1000p/50v_4  [C0402]  142.68 136.29 90 bottom
C1162  *150u/6.3v_3528  [C3528]  179 99.71 270 bottom
C1163  10u/6.3v_6  [C0603]  179.13 91.46 0 bottom
C1164  0.1u/10v_4  [C0402]  179 90.19 0 bottom
C1165  10u/6.3v_6  [C0603]  176.21 93.24 90 bottom
C1166  0.1u/10v_4  [C0402]  174.3 93.75 0 bottom
C1167  0.1u/10v_4  [C0402]  174.3 92.73 0 bottom
C1168  0.1u/10v_4  [C0402]  157.66 93.49 90 bottom
C1169  0.1u/10v_4  [C0402]  156.52 93.49 90 bottom
C1176  0.1u/10v_4  [C0402]  166.43 107.84 90 bottom
C1177  0.1u/10v_4  [C0402]  165.41 107.84 90 bottom
C1244  1u/6.3v_4  [C0402]  130.99 40.91 180 bottom
C1245  1u/6.3v_4  [C0402]  147 41.29 0 top
C1246  10u/6.3v_6  [C0603]  134.93 51.33 180 top
C1247  10u/6.3v_6  [C0603]  144.46 53.87 270 top
C1248  10u/6.3v_6  [C0603]  90.35 51.45 0 top
C1249  1u/6.3v_4  [C0402]  147 44.09 0 top
C1250  10u/6.3v_6  [C0603]  126.29 44.85 90 top
C1251  1u/6.3v_4  [C0402]  147 42.18 0 top
C1252  0.022u/25v_4  [C0402]  128.96 38.37 180 top
C1253  1u/6.3v_4  [C0402]  121.85 40.41 180 bottom
C1254  1u/6.3v_4  [C0402]  105.21 41.04 0 bottom
C1255  10u/6.3v_6  [C0603]  126.55 40.28 90 top
C1256  1u/6.3v_4  [C0402]  111.44 40.91 180 bottom
C1257  10u/6.3v_6  [C0603]  148.77 48.15 90 top
C1258  *0.1u/10v_4  [C0402]  110.04 43.83 0 top
C1259  0.1u/16v_4  [C0402]  125.28 40.53 90 top
C1260  1u/6.3v_4  [C0402]  134.8 40.91 180 bottom
C1261  1u/6.3v_4  [C0402]  101.15 41.04 180 bottom
C1262  10u/6.3v_6  [C0603]  124.01 43.2 90 top
C1263  10u/6.3v_6  [C0603]  93.4 51.45 180 top
C1264  10u/6.3v_6  [C0603]  112.2 60.22 270 top
C1265  10u/6.3v_6  [C0603]  155.76 50.44 180 top
C1266  0.1u/16v_4  [C0402]  147.76 48.03 90 top
C1267  0.1u/10v_4  [C0402]  155.5 51.58 180 top
C1268  10u/6.3v_6  [C0603]  155.89 48.03 180 top
C1270  10u/6.3v_6  [C0603]  147.12 45.36 0 top
C1271  1u/6.3v_4  [C0402]  84.38 41.04 0 bottom
C1272  10u/6.3v_6  [C0603]  139.38 53.49 90 top
C1273  1u/6.3v_4  [C0402]  115.12 40.91 0 bottom
C1275  1u/6.3v_4  [C0402]  147 43.07 0 top
C1276  0.1u/16v_4  [C0402]  155.63 49.3 180 top
C1308  10u/6.3v_6  [C0603]  134.42 63.14 180 top
C1309  1u/6.3v_4  [C0402]  145.34 67.46 270 bottom
C1310  1u/6.3v_4  [C0402]  146.87 53.74 0 top
C1311  1u/6.3v_4  [C0402]  146.87 54.76 0 top
C1312  10u/6.3v_6  [C0603]  95.31 55.39 0 top
C1313  10u/6.3v_6  [C0603]  116.9 67.2 0 top
C1314  1u/6.3v_4  [C0402]  126.93 66.57 270 bottom
C1315  1u/6.3v_4  [C0402]  146.87 55.77 0 top
C1316  10u/6.3v_6  [C0603]  155.76 58.31 180 top
C1317  *0.1u/10v_4  [C0402]  110.29 56.79 90 top
C1318  1u/6.3v_4  [C0402]  110.55 66.44 0 top
C1319  1u/6.3v_4  [C0402]  146.87 51.84 0 top
C1320  0.1u/16v_4  [C0402]  147.76 60.73 90 top
C1321  10u/6.3v_6  [C0603]  114.23 67.2 180 top
C1322  10u/6.3v_6  [C0603]  155.76 63.52 180 top
C1323  0.1u/16v_4  [C0402]  117.28 63.77 0 top
C1324  10u/6.3v_6  [C0603]  148.9 60.34 90 top
C1325  1u/6.3v_4  [C0402]  120.58 68.22 0 bottom
C1326  0.1u/16v_4  [C0402]  155.38 59.71 180 top
C1327  10u/6.3v_6  [C0603]  116.9 62.5 0 top
C1328  10u/6.3v_6  [C0603]  145.09 62.88 180 top
C1329  0.022u/25v_4  [C0402]  113.34 59.84 270 top
C1330  10u/6.3v_6  [C0603]  100.89 51.33 180 top
C1331  10u/6.3v_6  [C0603]  113.59 63.52 180 top
C1332  1u/6.3v_4  [C0402]  99.62 65.3 90 top
C1333  1u/6.3v_4  [C0402]  146.87 52.85 0 top
C1334  10u/6.3v_6  [C0603]  138.74 55.65 0 top
C1335  1u/6.3v_4  [C0402]  132.9 67.2 270 bottom
C1336  1u/6.3v_4  [C0402]  117.02 67.46 0 bottom
C1337  1u/6.3v_4  [C0402]  89.85 67.08 270 top
C1338  0.1u/10v_4  [C0402]  155.38 64.66 180 top
C3000  fpd@4.7u/6.3v_4  [C0402]  112.32 30.12 0 top
C3001  *fpd@2.2u/16v_6  [C0603]  109.78 33.55 90 top
C3002  fpd@0.01u/50v_4  [C0402]  115.92 18.92 0 bottom
C3007  *fpd_sp@0.01u/50v_4  [C0402]  107.5 21.74 270 bottom
C3008  *fpd_sp@0.1u/16v/x7r_4  [C0402]  106.61 21.74 270 bottom
C3224  .1u/16v_4  [C0402]  129.09 175.53 315 bottom
C3225  .1u/16v_4  [C0402]  129.72 176.17 315 bottom
C3226  .1u/16v_4  [C0402]  130.99 177.44 315 bottom
C3227  .1u/16v_4  [C0402]  130.36 176.8 315 bottom
C4000  ev@22u/6.3v_6  [C0603]  175.7 130.45 0 top
C4001  ev@22u/6.3v_6  [C0603]  167.32 136.54 180 top
C4002  ev@22u/6.3v_6  [C0603]  167.32 135.15 180 top
C4003  ev@22u/6.3v_6  [C0603]  175.7 135.4 0 top
C4004  ev@10u/6.3v_6  [C0603]  175.82 137.69 180 top
C4005  ev@10u/6.3v_6  [C0603]  165.41 120.29 180 top
C4006  ev@10u/6.3v_6  [C0603]  167.32 133.75 0 top
C4007  ev@10u/6.3v_6  [C0603]  167.32 132.35 0 top
C4008  ev@1u/6.3v_4  [C0402]  167.06 138.7 180 top
C4009  ev@1u/6.3v_4  [C0402]  175.57 132.86 0 top
C4010  ev@1u/6.3v_4  [C0402]  167.06 137.69 180 top
C4011  ev@1u/6.3v_4  [C0402]  175.44 136.54 0 top
C4012  ev@4.7u/6.3v_4  [C0402]  175.72 134.08 0 top
C4013  ev@0.022u/25v_4  [C0402]  171.89 113.81 90 top
C4014  ev@4.7u/6.3v_4  [C0402]  175.7 131.85 0 top
C4015  ev@0.22u/10v_4  [C0402]  161.5 124.17 180 top
C4016  ev@0.22u/10v_4  [C0402]  161.5 123.15 180 top
C4017  ev@0.22u/10v_4  [C0402]  165.54 125.11 180 top
C4018  ev@0.22u/10v_4  [C0402]  165.54 124.1 180 top
C4019  ev@0.022u/25v_4  [C0402]  170.87 113.81 270 top
C4020  ev@0.22u/10v_4  [C0402]  161.47 126.38 180 top
C4021  ev@0.22u/10v_4  [C0402]  161.47 125.37 180 top
C4022  ev@0.22u/10v_4  [C0402]  161.47 128.42 180 top
C4023  ev@0.22u/10v_4  [C0402]  161.47 127.4 180 top
C4024  gc6@0.1u/16v_4  [C0402]  214.31 106.45 0 bottom
C4025  gc6@0.1u/16v_4  [C0402]  220.03 106.05 0 bottom
C4026  ev@4.7u/6.3v_4  [C0402]  183.32 125.5 90 top
C4027  ev@1u/6.3v_4  [C0402]  188.14 122.57 90 top
C4028  ev@0.1u/16v_4  [C0402]  184.33 125.5 90 top
C4029  *ev@0.1u/16v_4  [C0402]  185.35 125.5 90 top
C4030  ev@1000p/50v_4  [C0402]  208.22 107.2 180 bottom
C4031  *ev@0.1u/16v_4  [C0402]  188.65 125.5 90 top
C4032  ev@4.7u/6.3v_4  [C0402]  176.36 127.22 180 top
C4033  ev@1u/6.3v_4  [C0402]  178.62 127.4 180 top
C4034  ev@0.1u/16v_4  [C0402]  186.62 125.5 90 top
C4035  ev@0.1u/16v_4  [C0402]  187.64 125.5 90 top
C4036  ev@4.7u/6.3v_4  [C0402]  163 144.67 0 bottom
C4037  ev@1u/6.3v_4  [C0402]  175.72 138.72 0 top
C4038  ev@0.1u/16v_4  [C0402]  174.83 127.6 270 top
C4039  ev@4.7u/6.3v_4  [C0402]  178.67 128.62 180 top
C4040  ev@0.1u/16v_4  [C0402]  175.72 139.87 180 top
C4041  ev@4.7u/6.3v_4  [C0402]  186.24 112.8 270 top
C4100  ev@1u/6.3v_4  [C0402]  180.47 138.96 270 top
C4101  ev@1u/6.3v_4  [C0402]  184.33 138.96 270 top
C4102  ev@1u/6.3v_4  [C0402]  186.87 138.96 270 top
C4103  ev@1u/6.3v_4  [C0402]  185.6 138.96 270 top
C4104  ev@0.1u/16v_4  [C0402]  189.06 131.16 180 top
C4105  ev@0.1u/16v_4  [C0402]  189.06 130.14 180 top
C4106  ev@0.1u/16v_4  [C0402]  203.51 168.93 0 bottom
C4107  ev@0.1u/16v_4  [C0402]  203.51 166.9 0 top
C4108  ev@4.7u/6.3v_4  [C0402]  179 138.96 270 top
C4109  ev@4.7u/6.3v_4  [C0402]  189.79 126.26 270 top
C4110  ev@4.7u/6.3v_4  [C0402]  189.06 133.44 180 top
C4111  ev@10u/6.3v_6  [C0603]  177.22 171.47 180 bottom
C4112  ev@0.1u/16v_4  [C0402]  189.03 132.1 180 top
C4113  ev@4.7u/6.3v_4  [C0402]  177.6 138.93 270 top
C4114  ev@0.1u/16v_4  [C0402]  183.32 138.96 90 top
C4115  ev@10u/6.3v_4  [C0402]  189.67 136.29 90 top
C4116  ev@0.1u/16v_4  [C0402]  166.17 140.48 90 top
C4117  *ev@10u/6.3v_4  [C0402]  188.21 128.06 270 top
C4118  ev@10u/6.3v_4  [C0402]  181.59 137.61 0 top
C4119  ev@22u/6.3v_6  [C0603]  205.03 131.72 180 top
C4200  ev@1000p/50v_4  [C0402]  175.91 106.41 90 bottom
C4201  *ev@1000p/50v_4  [C0402]  171.89 108.6 0 bottom
C4202  ev@1000p/50v_4  [C0402]  161.45 134 270 bottom
C4203  *ev@1000p/50v_4  [C0402]  162.49 141.75 0 bottom
C4204  ev@22u/6.3v_6  [C0603]  171.76 123.21 0 top
C4205  ev@0.1u/16v_4  [C0402]  177.22 125.5 90 top
C4206  ev@10p/50v_4  [C0402]  192.08 114.6 180 top
C4207  ev@10p/50v_4  [C0402]  194.11 114.6 0 top
C4208  ev@22u/6.3v_6  [C0603]  165.79 122.32 90 top
C4209  ev@4.7u/6.3v_4  [C0402]  167.19 123.08 90 top
C4210  ev@0.1u/16v_4  [C0402]  176.08 125.5 90 top
C4211  ev@0.1u/16v_4  [C0402]  175.06 125.5 90 top
C4400  ev@1u/6.3v_4  [C0402]  185.22 127.53 0 top
C4401  ev@1u/6.3v_4  [C0402]  179.13 126.26 180 top
C4402  ev@1u/6.3v_4  [C0402]  180.55 127.47 90 top
C4403  ev@1u/6.3v_4  [C0402]  187.03 129.89 0 top
C4404  ev@1u/6.3v_4  [C0402]  184.21 133.37 90 top
C4405  ev@1u/6.3v_4  [C0402]  178.9 130.27 180 top
C4406  ev@1u/6.3v_4  [C0402]  180.55 129.5 90 top
C4407  ev@1u/6.3v_4  [C0402]  177.86 131.59 90 top
C4408  ev@4.7u/6.3v_4  [C0402]  182.56 132.61 180 top
C4409  ev@4.7u/6.3v_4  [C0402]  182.05 130.55 270 top
C4410  ev@4.7u/6.3v_4  [C0402]  179.15 125.14 0 top
C4411  ev@4.7u/6.3v_4  [C0402]  182.17 135.02 90 top
C4412  ev@4.7u/6.3v_4  [C0402]  175.57 115.08 0 top
C4413  sp@4.7u/6.3v_4  [C0402]  178.62 137.31 0 top
C4414  ev@4.7u/6.3v_4  [C0402]  178.75 116.61 180 top
C4415  ev@4.7u/6.3v_4  [C0402]  188.04 136.36 270 top
C4416  ev@4.7u/6.3v_4  [C0402]  186.9 133.65 0 top
C4417  sp@4.7u/6.3v_4  [C0402]  175.57 116.61 0 top
C4418  ev@4.7u/6.3v_4  [C0402]  186.14 136.36 270 top
C4419  sp@4.7u/6.3v_4  [C0402]  184.21 136.42 270 top
C4420  *ev@4.7u/6.3v_4  [C0402]  178.75 115.08 180 top
C4421  ev@4.7u/6.3v_4  [C0402]  178.75 134.64 0 top
C4422  ev@4.7u/6.3v_4  [C0402]  175.57 115.08 0 bottom
C4423  ev@10u/6.3v_4  [C0402]  183.44 127.78 270 top
C4424  ev@22u/6.3v_6  [C0603]  175.57 113.56 180 top
C4425  ev@22u/6.3v_6  [C0603]  179.63 131.46 180 top
C4426  ev@10u/6.3v_4  [C0402]  186.21 131.06 180 top
C4427  ev@22u/6.3v_6  [C0603]  178.75 113.56 0 top
C4428  ev@22u/6.3v_6  [C0603]  178.75 115.08 0 bottom
C4429  ev@22u/6.3v_6  [C0603]  175.57 113.56 180 bottom
C4430  ev@4.7u/6.3v_4  [C0402]  178.75 113.56 180 bottom
C4431  ev@4.7u/6.3v_4  [C0402]  175.57 112.03 0 top
C4432  *ev@4.7u/6.3v_4  [C0402]  175.57 110.51 0 top
C4433  ev@4.7u/6.3v_4  [C0402]  178.75 110.51 180 top
C4434  ev@4.7u/6.3v_4  [C0402]  178.75 112.03 180 top
C4435  330u/2v_7343  [CC7343]  171.51 119.78 180 top
C4512  gkb@1u/6.3v_4  [C0402]  169.35 171.6 90 bottom
C4513  gkb@1u/6.3v_4  [C0402]  185.48 169.44 90 top
C4514  gkb@0.1u/16v_4  [C0402]  185.48 156.99 90 top
C4515  gkb@1u/6.3v_4  [C0402]  165.28 157.37 180 bottom
C4516  gkb@1u/6.3v_4  [C0402]  165.28 169.82 180 bottom
C4517  gkb@1u/6.3v_4  [C0402]  183.95 169.44 90 top
C4518  gkb@1u/6.3v_4  [C0402]  183.95 156.99 270 top
C4519  gkb@1u/6.3v_4  [C0402]  168.2 171.6 90 top
C4520  gkb@1u/6.3v_4  [C0402]  170.49 171.6 90 bottom
C4521  gkb@1u/6.3v_4  [C0402]  203.51 158.64 0 top
C4522  gkb@1u/6.3v_4  [C0402]  185.48 159.02 270 top
C4523  gkb@330u/2v_7343  [CC7343]  222.18 155.59 90 bottom
C4524  gkb@1u/6.3v_4  [C0402]  177.98 171.6 90 top
C4525  gkb@1u/6.3v_4  [C0402]  175.06 171.6 90 bottom
C4526  gkb@1u/6.3v_4  [C0402]  203.51 159.66 0 top
C4527  gkb@1u/6.3v_4  [C0402]  183.95 159.02 270 top
C4528  gkb@0.047u/10v_4  [C0402]  165.28 168.68 0 bottom
C4529  gkb@0.047u/10v_4  [C0402]  165.28 159.4 180 top
C4530  gkb@0.1u/16v_4  [C0402]  203.51 167.91 180 top
C4531  gkb@0.047u/10v_4  [C0402]  185.48 161.06 90 top
C4532  gkb@0.1u/16v_4  [C0402]  168.2 171.6 270 bottom
C4533  gkb@0.047u/10v_4  [C0402]  189.03 171.72 270 top
C4534  gkb@0.047u/10v_4  [C0402]  165.28 160.55 180 top
C4535  gkb@0.1u/16v_4  [C0402]  203.51 165.75 180 bottom
C4536  gkb@0.047u/10v_4  [C0402]  183.95 161.06 90 top
C4537  gkb@10u/6.3v_6  [C0603]  199.07 171.85 270 top
C4538  gkb@0.1u/16v_4  [C0402]  203.51 166.9 180 bottom
C4539  gkb@0.1u/16v_4  [C0402]  170.49 171.6 270 top
C4540  gkb@0.1u/16v_4  [C0402]  201.48 171.85 270 top
C4541  gkb@0.1u/16v_4  [C0402]  185.48 167.41 270 top
C4542  gkb@10u/6.3v_6  [C0603]  164.9 162.83 0 top
C4543  gkb@0.1u/16v_4  [C0402]  203.51 167.91 180 bottom
C4544  gkb@0.1u/16v_4  [C0402]  169.35 171.6 270 top
C4545  *gkb@0.1u/16v_4  [C0402]  203.51 168.93 180 top
C4546  gkb@0.1u/16v_4  [C0402]  183.95 167.41 270 top
C4547  gkb@10u/6.3v_6  [C0603]  173.16 171.47 180 bottom
C4548  gkb@0.1u/16v_4  [C0402]  203.51 169.95 180 bottom
C4549  gkb@0.1u/16v_4  [C0402]  182.05 171.72 270 top
C4550  *gkb@0.1u/16v_4  [C0402]  200.34 171.85 270 top
C4551  gkb@0.1u/16v_4  [C0402]  183.95 165.37 270 top
C4552  gkb@0.1u/16v_4  [C0402]  203.51 160.67 0 top
C4553  gkb@0.1u/16v_4  [C0402]  165.28 158.39 0 bottom
C4554  *gkb@0.1u/16v_4  [C0402]  185.6 171.72 270 top
C4555  gkb@0.1u/16v_4  [C0402]  185.48 165.37 270 top
C4596  1u/6.3v_4  [C0402]  31.93 72.28 270 top
C4597  *4.7u/6.3v_4  [C0402]  33.13 67.08 180 top
C4598  0.1u/16v_4  [C0402]  35.24 67.2 270 top
C4599  0.1u/16v_4  [C0402]  41.33 67.33 0 top
C4600  4.7u/6.3v_4  [C0402]  40.32 65.04 270 top
C4601  0.1u/16v_4  [C0402]  32.95 69.11 0 top
C4602  0.1u/16v_4  [C0402]  32.95 68.22 0 top
C4603  *10p/50v_4  [C0402]  43.49 71.27 180 top
C4604  *10p/50v_4  [C0402]  43.49 70 180 top
C4605  10p/50v_4  [C0402]  43.36 74.7 90 top
C4606  10p/50v_4  [C0402]  43.36 72.79 270 top
C4607  0.1u/16v_4_x7r  [C0402]  21.65 43.33 90 top
C4608  0.1u/16v_4_x7r  [C0402]  16.19 43.33 90 top
C4609  0.1u/16v_4_x7r  [C0402]  19.87 43.33 90 top
C4611  *10p/50v_4  [C0402]  29.01 24.66 180 top
C4612  *10p/50v_4  [C0402]  30.92 24.66 180 top
C4613  *10p/50v_4  [C0402]  42.22 24.66 0 top
C4614  *10p/50v_4  [C0402]  39.43 24.66 0 top
C4615  *10p/50v_4  [C0402]  44.76 24.53 0 top
C4616  10p/50v_4  [C0402]  32.82 25.55 0 top
C4617  0.1u/16v_4  [C0402]  34.6 25.04 270 top
C4618  4.7u/6.3v_4  [C0402]  35.62 25.04 90 top
C4647  tyc@0.47u/25v_6  [C0603]  11.23 118.38 180 bottom
C4648  tyc@0.47u/25v_6  [C0603]  11.23 118.46 0 top
C4649  tyc@0.47u/25v_6  [C0603]  11.23 120.42 180 bottom
C4650  tyc@0.47u/25v_6  [C0603]  11.23 120.42 0 top
C4664  0.1u/10v_4  [C0402]  163 107.72 90 bottom
C4665  0.1u/10v_4  [C0402]  161.98 107.72 90 bottom
C4666  gka@0.1u/16v_4  [C0402]  210.5 113.3 90 bottom
C4667  gka@0.047u/10v_4  [C0402]  207.45 131.97 0 top
C4668  gka@1u/6.3v_4  [C0402]  219 151.66 90 top
C4669  gka@0.047u/10v_4  [C0402]  209.35 113.3 90 bottom
C4670  gka@0.1u/16v_4  [C0402]  222.05 133.37 180 top
C4671  gka@0.1u/16v_4  [C0402]  222.94 141.5 180 top
C4672  gka@1u/6.3v_4  [C0402]  211.51 133.37 180 top
C4673  gka@0.1u/16v_4  [C0402]  223.07 130.07 180 top
C4674  gka@10u/6.3v_6  [C0603]  206.3 153.94 270 bottom
C4675  gka@1u/6.3v_4  [C0402]  223.07 119.15 0 top
C4676  gka@1u/6.3v_4  [C0402]  209.86 151.66 90 top
C4677  gka@0.1u/16v_4  [C0402]  217.61 133.37 180 top
C4678  gka@0.1u/16v_4  [C0402]  211.51 131.97 0 top
C4679  gka@1u/6.3v_4  [C0402]  219.64 133.37 0 top
C4680  *gka@0.1u/16v_4  [C0402]  222.94 140.48 180 top
C4681  gka@0.1u/16v_4  [C0402]  217.61 131.97 180 top
